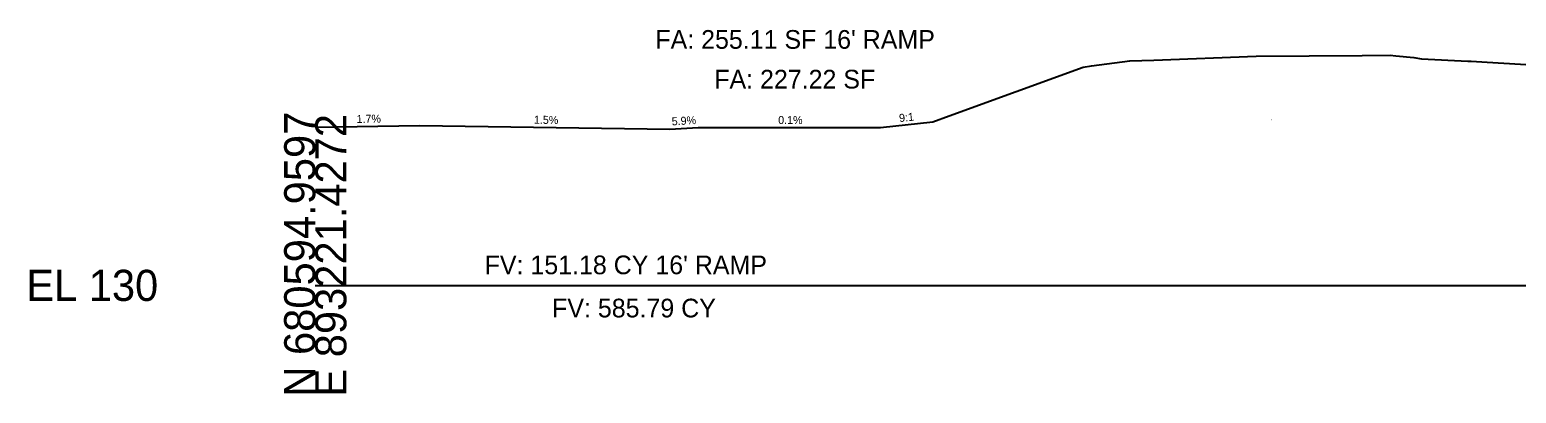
# Model space of a CAD drawing. Extents: x -26 to 4303, y -13 to 10775.
# Drawn here: x -25.7 to 108.1, y 6490.3 to 6523 of the extents above; entities that cross this region are included whole.
import ezdxf

# ---------------------------------------------------------------- set-up
doc = ezdxf.new("R2010")
doc.units = 0
for name, color, linetype in [('Draft_XS_Grid', 7, 'Continuous'), ('DTM_CORRIDOR', 7, 'Continuous'), ('DTM_X_GROUND', 7, 'Continuous'), ('SLOPE_STAKES_FILL', 7, 'Continuous'), ('XS_CELL', 7, 'Continuous'), ('XS_M_SHAPES_EARTHWORK', 7, 'Continuous'), ('XS_P_TX_FS_BS', 7, 'Continuous'), ('XS_SHEET_EW_TX_VOLUME', 7, 'Continuous')]:
    doc.layers.add(name, color=color, linetype=linetype)

msp = doc.modelspace()

# ---------------------------------------------------------------- linework, layer by layer
at = {"layer": 'DTM_X_GROUND'}
msp.add_lwpolyline([(0, 6514.23), (9.41, 6514.38), (31.89, 6514.05), (34.46, 6514.2), (50.85, 6514.19), (55.57, 6514.69), (57.03, 6515.24), (69.09, 6519.62), (69.83, 6519.72), (73.29, 6520.17), (75.44, 6520.25), (84.67, 6520.61), (94.2, 6520.67), (96.71, 6520.68), (97.23, 6520.62), (98.85, 6520.48), (99.53, 6520.37), (103.71, 6520.16), (104, 6520.15), (105.46, 6520.07), (110.94, 6519.73)], dxfattribs=at)
at = {"layer": 'XS_CELL'}
msp.add_line((0, 6500), (150, 6500), dxfattribs=at)

# ---------------------------------------------------------------- texts
at = {"layer": 'Draft_XS_Grid'}
msp.add_text('-', height=0.0001, dxfattribs=at).set_placement((0, 6500))
at = {"layer": 'DTM_CORRIDOR'}
msp.add_text('X', height=0.12, dxfattribs=at).set_placement((50.9, 6514.14))
at = {"layer": 'SLOPE_STAKES_FILL'}
msp.add_text('X', height=0.12, dxfattribs=at).set_placement((85.98, 6514.84))
at = {"layer": 'XS_CELL'}
for s, p in [('N 680594.9597', (0, 6490)), ('E 893221.4272', (2.8, 6490))]:
    msp.add_text(s, height=2.8, rotation=90, dxfattribs=at).set_placement(p)
msp.add_text('EL 130', height=2.8, dxfattribs=at).set_placement((-26, 6498.6))
at = {"layer": 'XS_M_SHAPES_EARTHWORK'}
for s, p in [("FV: 151.18 CY 16' RAMP", (15.24, 6501)), ('FV: 585.79 CY', (21.31, 6497.12))]:
    msp.add_text(s, height=1.68, dxfattribs=at).set_placement(p)
at = {"layer": 'XS_P_TX_FS_BS'}
for s, rotation, p in [('1.7%', 0.9535, (3.72, 6514.59)), ('9:1', 6.0246, (52.57, 6514.67)), ('1.5%', 359.159, (19.67, 6514.53)), ('5.9%', 3.3604, (32.09, 6514.37)), ('0.1%', 359.9487, (41.65, 6514.5))]:
    msp.add_text(s, height=0.72, rotation=rotation, dxfattribs=at).set_placement(p)
at = {"layer": 'XS_SHEET_EW_TX_VOLUME'}
for s, p in [("FA: 255.11 SF 16' RAMP", (30.6, 6521.26)), ('FA: 227.22 SF', (35.9, 6517.69))]:
    msp.add_text(s, height=1.68, dxfattribs=at).set_placement(p)

doc.saveas('drawing.dxf')
